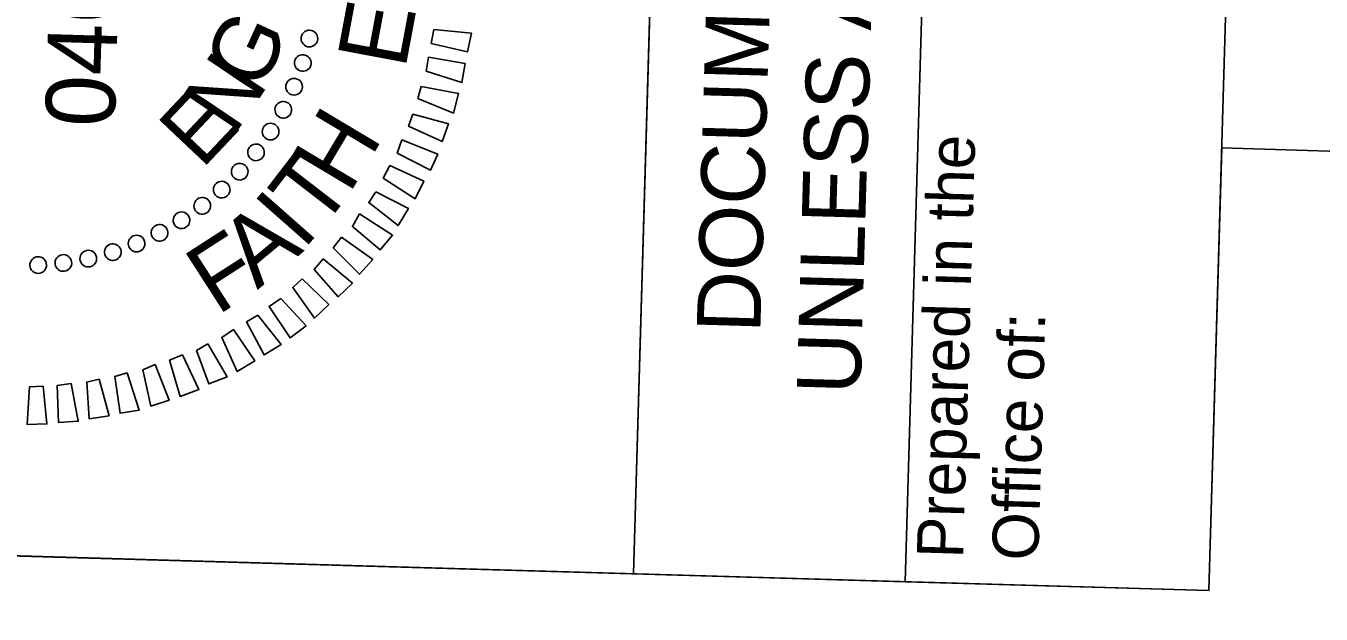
# Model space of a CAD drawing. Extents: x 2097422 to 2097881, y 685612 to 686386.
# Drawn here: x 2097482.75 to 2097527.53, y 686208.17 to 686228.48 of the extents above; entities that cross this region are included whole.
import ezdxf

# ---------------------------------------------------------------- set-up
doc = ezdxf.new("R2010")
doc.units = 0
for name, color, linetype in [('Scratch_Level_0', 7, 'Continuous'), ('Sheet Block Title CELL', 7, 'Continuous'), ('Sheet Layout Plan Border', 7, 'Continuous'), ('Sheet PE Seal Cell', 7, 'Continuous'), ('Sheet Profile CELL', 7, 'Continuous'), ('Sheet Sticker Exception Certification CELL', 7, 'Continuous')]:
    doc.layers.add(name, color=color, linetype=linetype)

msp = doc.modelspace()

# ---------------------------------------------------------------- linework, layer by layer
at = {"layer": 'Scratch_Level_0'}
msp.add_lwpolyline([(2097511.345, 685744.127), (2097439.862, 685904.988), (2097448.762, 686211.158), (2097523.653, 686208.981), (2097524.098, 686224.269), (2097869.03, 686214.241), (2097857.522, 685818.411), (2097708.276, 685751.241), (2097678.123, 685684.291), (2097536.101, 685688.42)], close=True, dxfattribs=at)
at = {"layer": 'Sheet Block Title CELL'}
msp.add_lwpolyline([(2097513.155, 686209.286), (2097515.481, 686289.276), (2097525.979, 686288.971), (2097523.653, 686208.981)], close=True, dxfattribs=at)
at = {"layer": 'Sheet Layout Plan Border'}
msp.add_lwpolyline([(2097566.717, 685687.53), (2097536.101, 685688.42), (2097439.862, 685904.988), (2097448.762, 686211.158), (2097459.26, 686210.853), (2097523.653, 686208.981), (2097524.098, 686224.269), (2097869.03, 686214.241), (2097857.522, 685818.411)], close=True, dxfattribs=at)
at = {"layer": 'Sheet PE Seal Cell'}
for p, q in [((2097492.546, 686228.041), (2097492.546, 686228.041)), ((2097492.342, 686227.207), (2097492.342, 686227.207)), ((2097492.038, 686226.375), (2097492.038, 686226.375)), ((2097491.655, 686225.586), (2097491.655, 686225.586)), ((2097491.232, 686224.818), (2097491.232, 686224.818)), ((2097490.711, 686224.113), (2097490.711, 686224.113)), ((2097490.151, 686223.429), (2097490.151, 686223.429)), ((2097489.533, 686222.827), (2097489.533, 686222.827)), ((2097488.856, 686222.246), (2097488.856, 686222.246)), ((2097488.142, 686221.767), (2097488.142, 686221.767)), ((2097487.369, 686221.329), (2097487.369, 686221.329)), ((2097486.578, 686220.952), (2097486.578, 686220.952)), ((2097484.038, 686220.305), (2097484.038, 686220.305)), ((2097484.922, 686220.44), (2097484.922, 686220.44)), ((2097485.769, 686220.655), (2097485.769, 686220.655)), ((2097483.175, 686220.21), (2097483.175, 686220.21))]:
    msp.add_line(p, q, dxfattribs=at)
for points in [[(2097496.857, 686228.356), (2097498.154, 686228.238), (2097498.015, 686227.582), (2097496.763, 686227.879)], [(2097496.669, 686227.401), (2097497.944, 686227.184), (2097497.824, 686226.527), (2097496.595, 686226.923)], [(2097496.42, 686226.388), (2097497.713, 686226.15), (2097497.534, 686225.475), (2097496.308, 686225.971)], [(2097496.132, 686225.436), (2097497.363, 686225.1), (2097497.145, 686224.486), (2097495.98, 686225.02)], [(2097495.746, 686224.547), (2097496.992, 686224.05), (2097496.736, 686223.498), (2097495.593, 686224.091)], [(2097495.34, 686223.658), (2097496.505, 686223.124), (2097496.207, 686222.512), (2097495.107, 686223.225)], [(2097494.854, 686222.752), (2097495.977, 686222.179), (2097495.62, 686221.589), (2097494.603, 686222.379)], [(2097494.291, 686221.988), (2097495.43, 686221.255), (2097494.995, 686220.747), (2097494.038, 686221.555)], [(2097493.668, 686221.186), (2097494.746, 686220.414), (2097494.291, 686219.907), (2097493.377, 686220.814)], [(2097493.026, 686220.444), (2097494.041, 686219.594), (2097493.548, 686219.128), (2097492.715, 686220.073)], [(2097492.305, 686219.745), (2097493.22, 686218.858), (2097492.726, 686218.392), (2097491.976, 686219.454)], [(2097491.565, 686219.066), (2097492.438, 686218.12), (2097491.886, 686217.716), (2097491.157, 686218.798)], [(2097490.768, 686218.489), (2097491.579, 686217.485), (2097490.988, 686217.122), (2097490.381, 686218.26)], [(2097489.933, 686217.993), (2097490.662, 686216.911), (2097490.051, 686216.549), (2097489.525, 686217.725)], [(2097488.167, 686217.124), (2097488.733, 686215.927), (2097488.085, 686215.686), (2097487.722, 686216.937)], [(2097489.038, 686217.499), (2097489.706, 686216.359), (2097489.078, 686216.117), (2097488.652, 686217.27)], [(2097487.217, 686216.791), (2097487.701, 686215.557), (2097487.075, 686215.355), (2097486.791, 686216.604)], [(2097485.282, 686216.287), (2097485.625, 686215.017), (2097484.942, 686214.917), (2097484.858, 686216.18)], [(2097486.248, 686216.499), (2097486.671, 686215.207), (2097486.008, 686215.106), (2097485.824, 686216.372)], [(2097483.354, 686216.043), (2097483.476, 686214.739), (2097482.795, 686214.719), (2097482.873, 686216.017)], [(2097484.317, 686216.135), (2097484.559, 686214.828), (2097483.877, 686214.788), (2097483.835, 686216.069)]]:
    msp.add_lwpolyline(points, close=True, dxfattribs=at)
for centre, major_axis in [((2097492.554, 686228.047), (0.281, -0.063)), ((2097492.325, 686227.202), (0.274, -0.087)), ((2097492.023, 686226.381), (0.266, -0.111)), ((2097491.651, 686225.588), (0.255, -0.134)), ((2097491.212, 686224.832), (0.242, -0.155)), ((2097490.707, 686224.116), (0.228, -0.176)), ((2097490.143, 686223.448), (0.212, -0.195)), ((2097489.522, 686222.83), (0.194, -0.213)), ((2097488.85, 686222.27), (0.175, -0.229)), ((2097488.132, 686221.77), (0.154, -0.243)), ((2097487.373, 686221.335), (0.132, -0.256)), ((2097486.579, 686220.967), (0.109, -0.266)), ((2097484.909, 686220.446), (0.062, -0.281)), ((2097485.755, 686220.67), (0.086, -0.275)), ((2097483.175, 686220.223), (0.012, -0.288)), ((2097484.047, 686220.296), (0.037, -0.286))]:
    msp.add_ellipse(centre, major_axis=major_axis, ratio=0.999708, dxfattribs=at)
at = {"layer": 'Sheet Profile CELL'}
msp.add_lwpolyline([(2097458.778, 686210.867), (2097459.941, 686250.87), (2097504.922, 686249.563), (2097503.759, 686209.559)], close=True, dxfattribs=at)
at = {"layer": 'Sheet Sticker Exception Certification CELL'}
for p, q in [((2097503.759, 686209.559), (2097506.084, 686289.541)), ((2097515.48, 686289.268), (2097513.155, 686209.286)), ((2097513.155, 686209.286), (2097503.759, 686209.559))]:
    msp.add_line(p, q, dxfattribs=at)

# ---------------------------------------------------------------- texts
at = {"layer": 'Sheet Block Title CELL'}
for s, height, p in [('Prepared in the ', 1.60046, (2097515.152, 686210.078)), ('Office of:', 1.6005, (2097517.752, 686210.002))]:
    msp.add_text(s, height=height, rotation=88.3348, dxfattribs=at).set_placement(p)
at = {"layer": 'Sheet PE Seal Cell'}
for s, height, rotation, p in [('046981', 2.3993, 88.3348, (2097485.817, 686224.967)), ('E', 2.399, 79.3925, (2097495.864, 686226.954)), ('G', 2.255, 65.3251, (2097490.891, 686226.169)), ('N', 2.255, 55.9688, (2097489.947, 686224.675)), ('E', 2.255, 46.6117, (2097488.833, 686223.507)), ('H', 2.399, 59.2082, (2097493.924, 686222.636)), ('T', 2.399, 52.4079, (2097492.944, 686221.369)), ('I', 2.399, 48.606, (2097492.333, 686220.714)), ('A', 2.399, 39.7657, (2097490.754, 686219.357)), ('F', 2.399, 32.7491, (2097489.364, 686218.462))]:
    msp.add_text(s, height=height, rotation=rotation, dxfattribs=at).set_placement(p)
at = {"layer": 'Sheet Sticker Exception Certification CELL'}
for s, p in [('UNLESS ALL SIGNATURES COMPLETED', (2097511.6, 686215.734)), ('DOCUMENT NOT CONSIDERED FINAL', (2097508.141, 686217.864))]:
    msp.add_text(s, height=2.2, rotation=88.3348, dxfattribs=at).set_placement(p)

doc.saveas('drawing.dxf')
